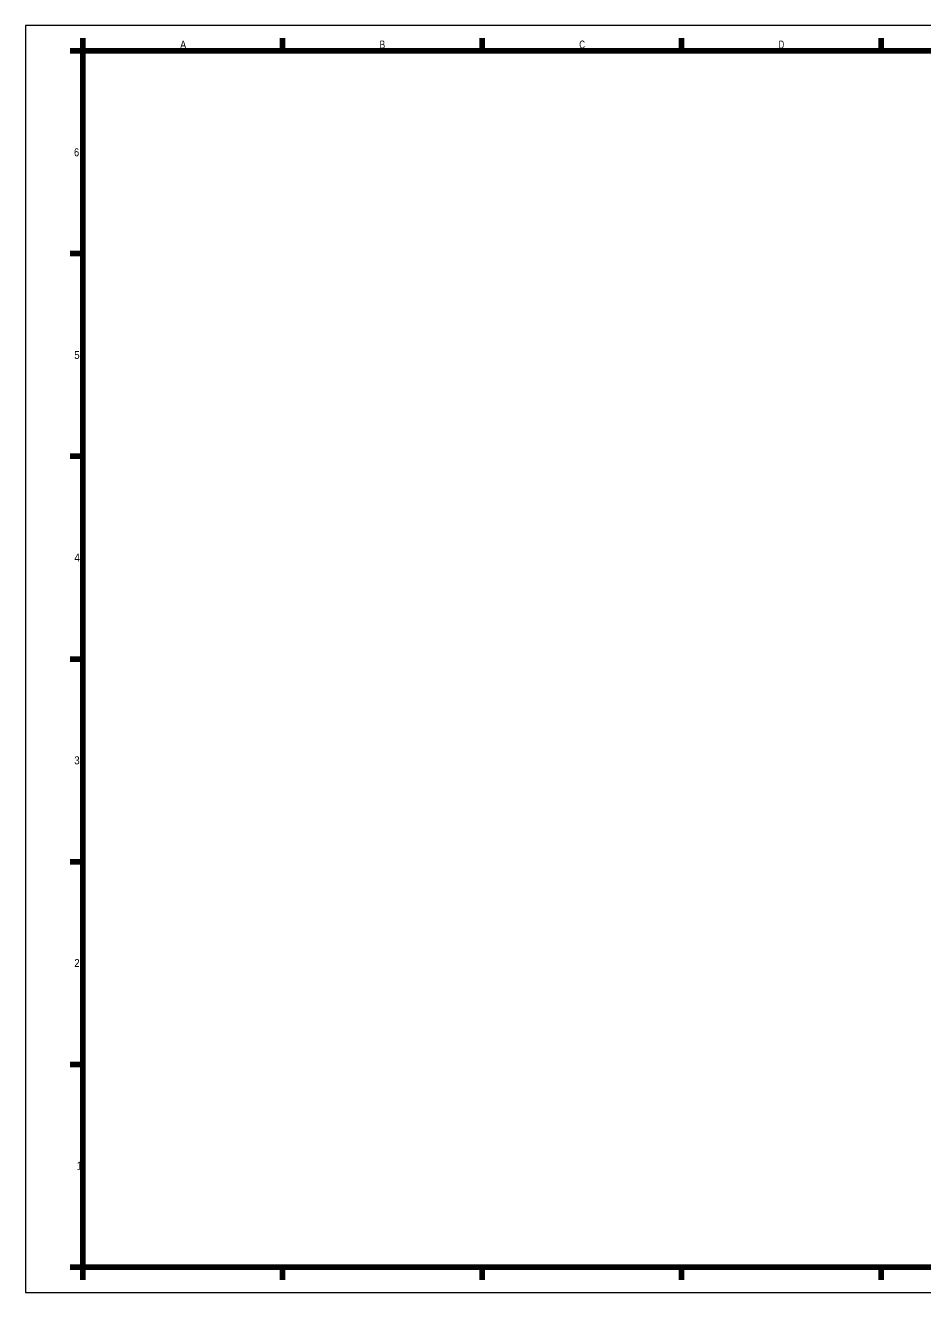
# Model space of a CAD drawing. Extents: x -202666 to -201825, y -108963 to -108369.
# Drawn here: x -202666 to -202246, y -108963 to -108369 of the extents above; entities that cross this region are included whole.
import ezdxf
from ezdxf.enums import TextEntityAlignment as Align

# ---------------------------------------------------------------- set-up
doc = ezdxf.new("R2010")
doc.units = 0
doc.header["$LTSCALE"] = 0.8
doc.layers.add('1', color=7, linetype='Continuous', lineweight=35)

msp = doc.modelspace()

# ---------------------------------------------------------------- linework, layer by layer
at = {"layer": '1', "lineweight": 90}
for p, q in [((-202545.613, -108375.444), (-202545.613, -108381.444)), ((-202452.113, -108375.444), (-202452.113, -108381.444)), ((-202358.613, -108375.444), (-202358.613, -108381.444)), ((-202265.113, -108375.444), (-202265.113, -108381.444)), ((-202639.113, -108951.444), (-202639.113, -108381.444)), ((-202639.113, -108476.444), (-202645.113, -108476.444)), ((-202639.113, -108571.444), (-202645.113, -108571.444)), ((-202639.113, -108666.444), (-202645.113, -108666.444)), ((-202639.113, -108761.444), (-202645.113, -108761.444)), ((-202639.113, -108856.444), (-202645.113, -108856.444)), ((-202639.113, -108951.444), (-202645.113, -108951.444)), ((-202639.113, -108951.444), (-202639.113, -108957.444)), ((-202545.613, -108951.444), (-202545.613, -108957.444)), ((-202452.113, -108951.444), (-202452.113, -108957.444)), ((-202358.613, -108951.444), (-202358.613, -108957.444)), ((-202265.113, -108951.444), (-202265.113, -108957.444))]:
    msp.add_line(p, q, dxfattribs=at)
at = {"layer": '1', "lineweight": 13}
msp.add_lwpolyline([(-202666.113, -108963.444), (-201825.113, -108963.444), (-201825.113, -108369.444), (-202666.113, -108369.444)], close=True, dxfattribs=at)
at = {"layer": '1', "lineweight": 90}
for points in [[(-202639.113, -108375.444), (-202639.113, -108381.444), (-202645.113, -108381.444)], [(-202639.113, -108381.444), (-201891.113, -108381.444), (-201837.113, -108381.444)], [(-201837.113, -108951.444), (-201891.113, -108951.444), (-202639.113, -108951.444)]]:
    msp.add_lwpolyline(points, dxfattribs=at)

# ---------------------------------------------------------------- texts
at = {"layer": '1'}
for s, width, p in [('A', 0.85, (-202592.1415, -108380.319)), ('B', 0.75, (-202498.7745, -108380.319)), ('C', 0.75, (-202405.186, -108380.319)), ('D', 0.7, (-202311.7745, -108380.319)), ('6', 0.85, (-202642.113, -108430.819)), ('5', 0.9, (-202641.9215, -108525.819)), ('4', 0.95, (-202641.833, -108620.819)), ('3', 0.9, (-202641.9215, -108715.819)), ('2', 0.9, (-202641.9215, -108810.819))]:
    msp.add_text(s, height=3.75, dxfattribs=dict(at, width=width)).set_placement(p, align=Align.CENTER)
msp.add_text('1', height=3.75, dxfattribs=at).set_placement((-202640.7064, -108905.819), align=Align.CENTER)

doc.saveas('drawing.dxf')
